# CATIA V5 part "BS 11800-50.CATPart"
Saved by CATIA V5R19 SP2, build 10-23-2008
Part number: BS 11800-50
Bounding box of the stored display mesh (mm): x -74.81 to 74.81, y -74.81 to 74.81, z 0 to 178
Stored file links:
  C:\Users\Bora\Desktop\3D Katı model\BS serisi\BS 11800\BS 11800-50.CATPart
  C:\Program Files\Dassault Systemes\B19\intel_a\reffiles\standard\MetricThickPitch.txt
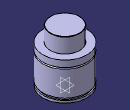
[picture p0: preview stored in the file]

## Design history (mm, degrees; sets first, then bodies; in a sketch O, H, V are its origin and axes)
Body1 (main body)
  Sketch1 on yz-plane, origin (0, 0, 0), H (0, 1, 0), V (0, 0, 1)
    point P1 (75, 105)
    point P2 (75, 100)
    point P5 (50, 177)
    point P7 (50, 177)
    point P12 (75, 100)
    point P13 (75, 105)
    arc A1 centre (75, 102.5) radius 2.5 from (75, 105) to (75, 100) ccw
    line L1 (75, 0) -> (75, 8)
    line L2 (50, 177) -> (50, 127)
    arc A2 centre (49, 177) radius 1 from (50, 177) to (49, 178) ccw
    line L3 (71, 15) -> (71, 8)
    line L4 (75, 15) -> (75, 100)
    line L5 (75, 105) -> (75, 127)
    line L6 (49, 178) -> (0, 178)
    point P15 (0, 178)
    line L7 (50, 127) -> (75, 127)
    line L8 (0, 0) -> (75, 0)
    line L9 (71, 15) -> (75, 15)
    line L10 (71, 8) -> (75, 8)
    coincidence: P15 V, P1 P13, P2 P12, P5 P7
    tangency: L6 A2
    horizontal: L7 H, L8 H, L9 H, L10 H
  Shaft1: profile Sketch1, axis Sketch1.V, angle 360
  Sketch2 on face of Shaft1 from Sketch1.L8, origin (0, 0, 0), H (1, 0, 0), V (0, -1, 0)
    point P1 (50, 0)
    distance P1 V = 50
  Hole1: placed by Sketch2, at (50, 0, 0) direction (0, 0, 1), diameter 8.376, depth 12, threaded "M10", thread diameter 10, thread depth 12, pitch 1.5
  CircPattern1: of Hole1, instances 4, angular step 90, axis from xy-plane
